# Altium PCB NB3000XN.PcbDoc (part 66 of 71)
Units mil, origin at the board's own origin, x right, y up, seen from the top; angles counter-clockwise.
Board outline 9527.56 x 6929.77 mil, 6 copper layers (Top Layer, GND+SHIELD, MidLayer1, MidLayer2, P2 - 3V3+5V0, Bottom Layer), stack 62.375 mil thick; 832 components, 1027 nets, 4655 pads, 4981 vias.
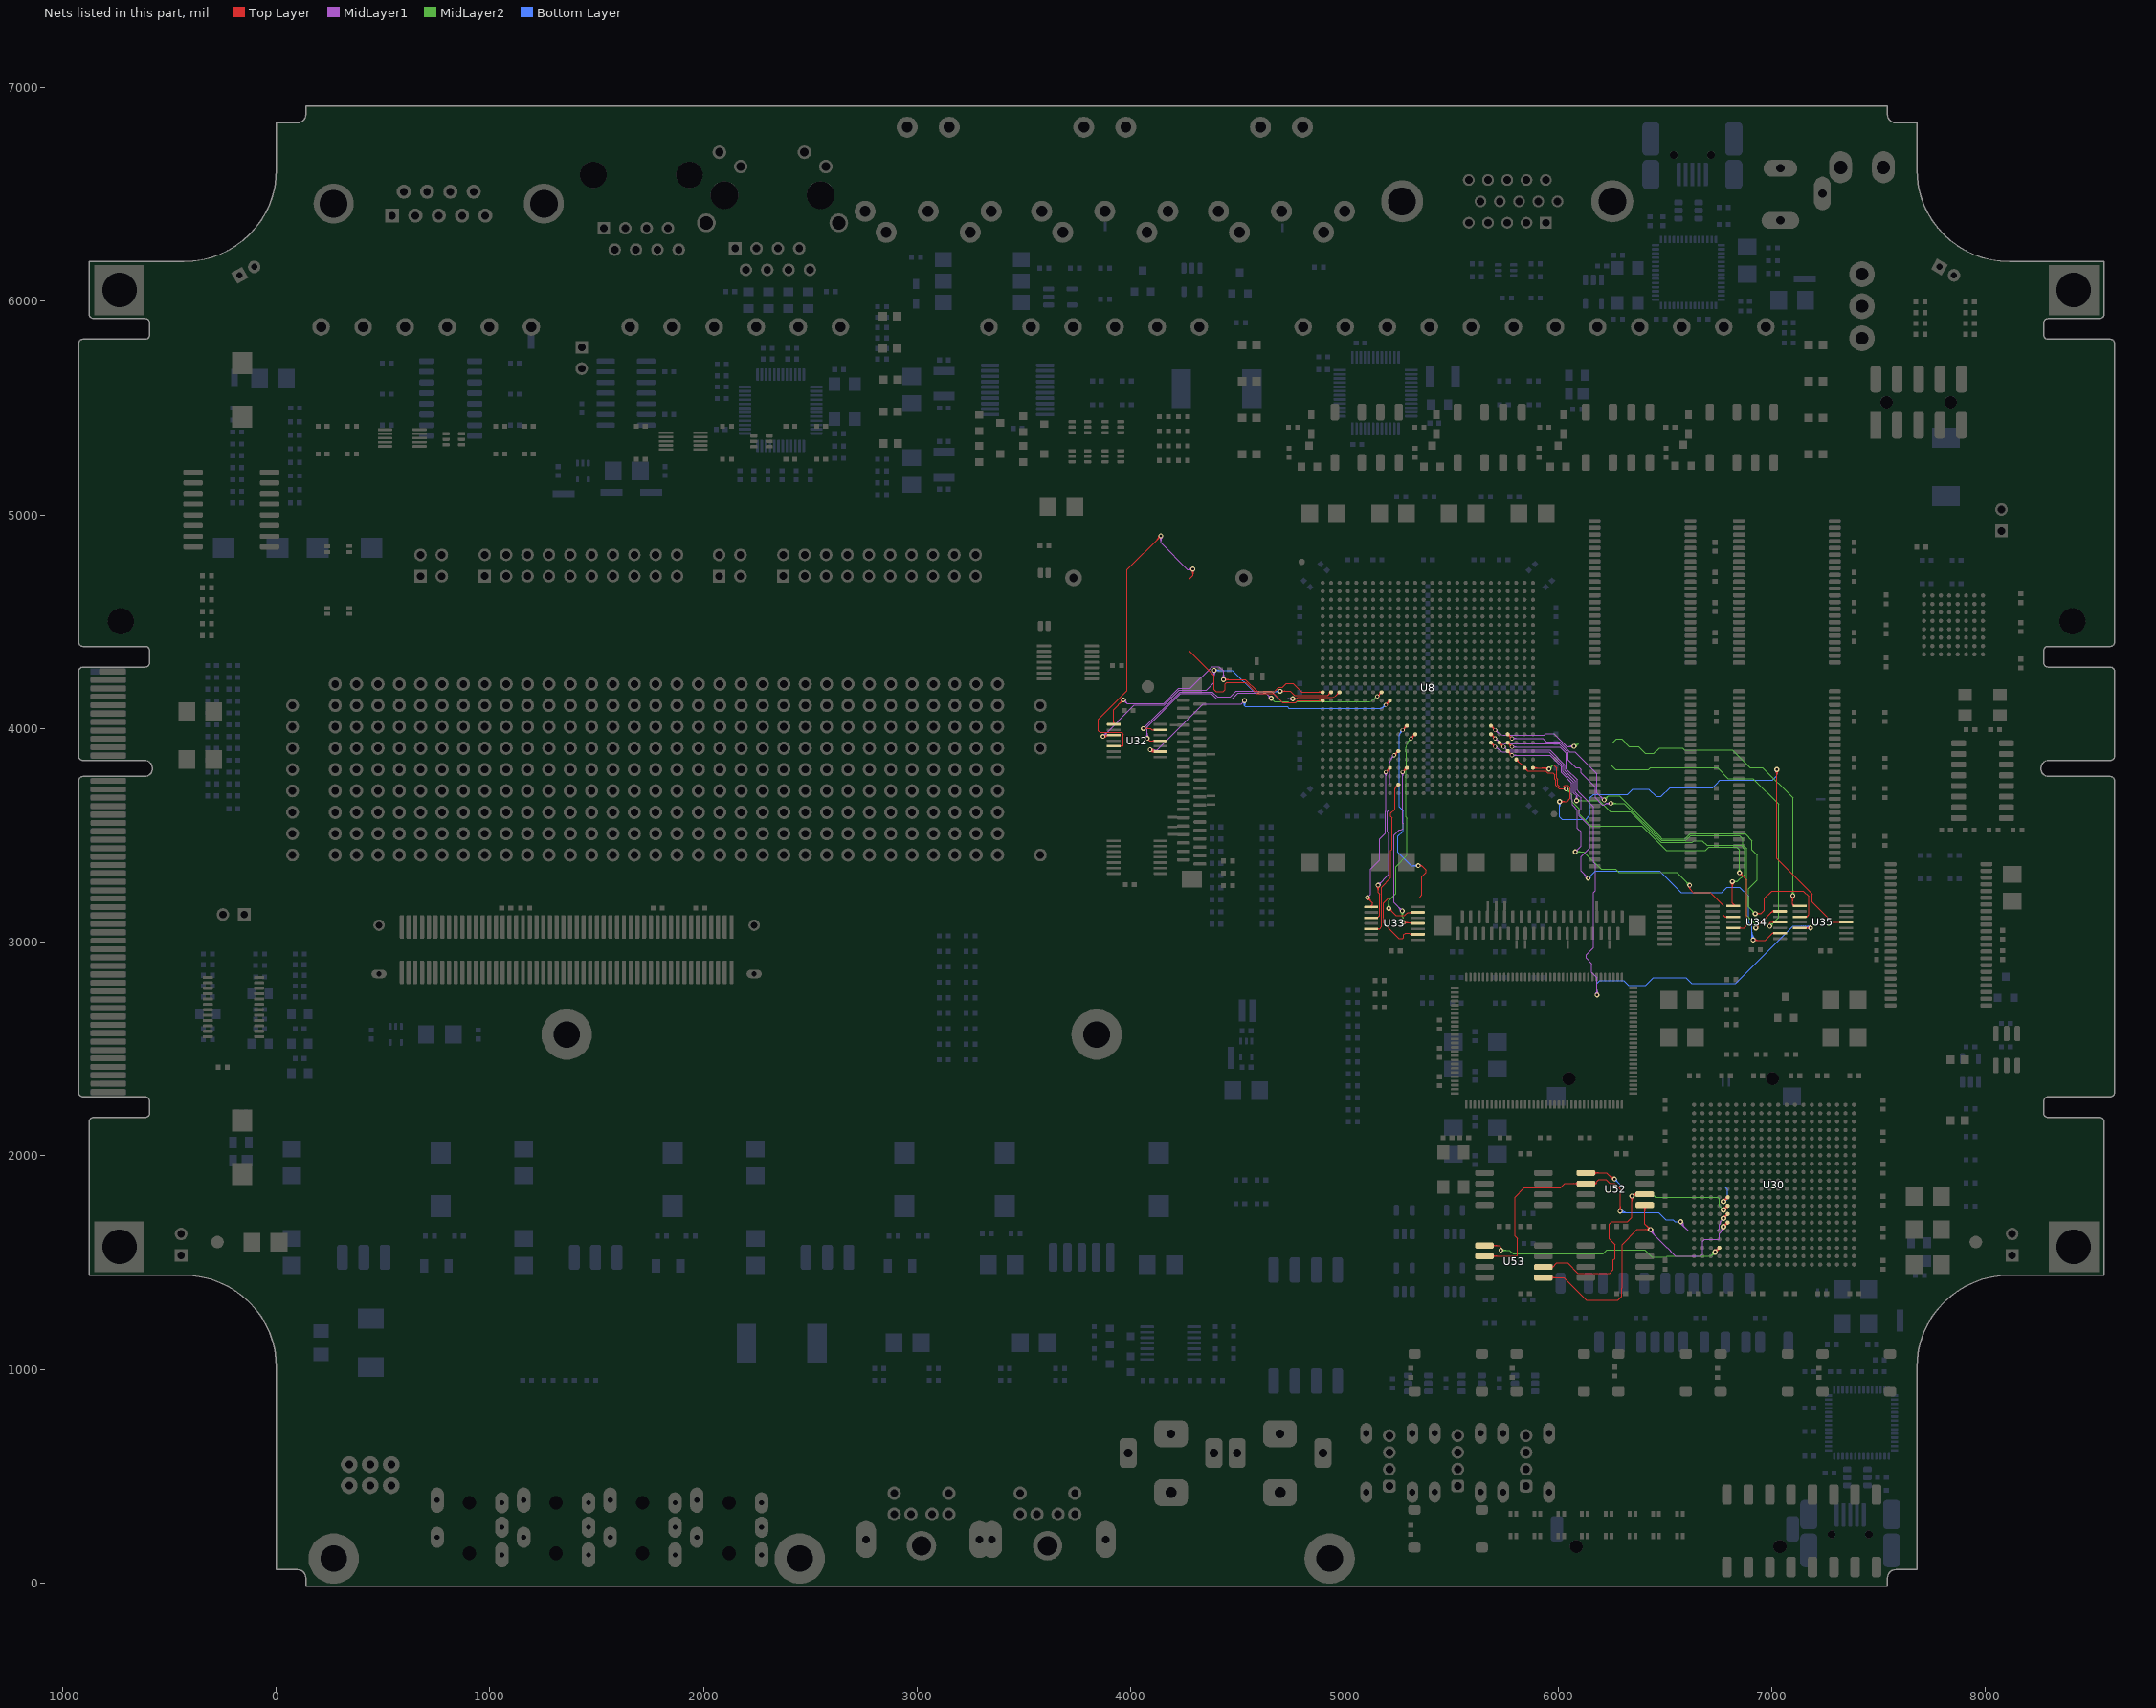
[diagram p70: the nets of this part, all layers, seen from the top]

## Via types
v1: diameter 23, hole 11.81, Top Layer to Bottom Layer, 3672 vias
v2: diameter 26, hole 11.81, Top Layer to Bottom Layer, 461 vias
v3: diameter 19, hole 11.81, Top Layer to Bottom Layer, tented both sides, 396 vias
v4: diameter 23.62, hole 11.81, Top Layer to Bottom Layer, 288 vias
v5: diameter 20, hole 11.81, Top Layer to Bottom Layer, 91 vias
v6: diameter 23, hole 11.81, Top Layer to Bottom Layer, tented both sides, 50 vias
v7: diameter 31, hole 11.81, Top Layer to Bottom Layer, 15 vias
v8: diameter 27.56, hole 11.81, Top Layer to Bottom Layer, tented both sides, 4 vias
v9: diameter 29, hole 11.81, Top Layer to Bottom Layer, 3 vias
v10: diameter 21, hole 11.81, Top Layer to Bottom Layer, 1 vias

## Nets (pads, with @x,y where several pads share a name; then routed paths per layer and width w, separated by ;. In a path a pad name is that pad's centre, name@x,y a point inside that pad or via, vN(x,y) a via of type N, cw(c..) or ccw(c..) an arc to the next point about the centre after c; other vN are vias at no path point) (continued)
USER_FLASH.DIN: U30.T15 U52.5 U53.5 | length 1959.8
  Top Layer w4: U53.5@5930.59,1430 6026.9,1430 6131.86,1325.04 6280.52,1325.04 6297.19,1341.71 6297.19,1380 6300,1382.81 6300,1585 6370.04,1655.04 v1(6431.86,1655.04) 6405.59,1681.31 U52.5@6405.59,1770 ; U53.5@5965.62,1424.5 cw(c5978.9,1411.22) 5978.9,1430 cw(c5978.9,1448.78) U53.5@5965.62,1435.5 ; U53.5@5968.45,1421.67 cw(c5988.56,1401.56) 5988.56,1430 cw(c5988.56,1458.44) U53.5@5968.45,1438.33 ; U52.5@6397.26,1761.67 cw(c6377.15,1741.56) 6405.59,1741.56 cw(c6434.03,1741.56) U52.5@6413.92,1761.67 ; U52.5@6400.09,1764.5 cw(c6386.81,1751.22) 6405.59,1751.22 cw(c6424.37,1751.22) U52.5@6411.09,1764.5 ; v1@6422.36,1655.04 ccw(c6399.42,1655.04) 6415.64,1671.26 ccw(c6431.86,1687.48) v1@6431.86,1664.54 ; v1@6425.14,1648.32 ccw(c6408.92,1632.11) 6408.92,1655.04 ccw(c6408.92,1677.98) v1@6425.14,1661.76 ; v1@6426.36,1655.04 ccw(c6413.08,1655.04) 6422.47,1664.43 ccw(c6431.86,1673.82) v1@6431.86,1660.54 ; v1@6427.97,1651.15 ccw(c6418.58,1641.76) 6418.58,1655.04 ccw(c6418.58,1668.32) v1@6427.97,1658.93
  Top Layer w8: v2(6773.78,1668.15) U30.T15@6793.46,1687.83 ; v2@6773.78,1677.15 ccw(c6773.78,1698.88) 6789.14,1683.51 ccw(c6804.51,1668.15) v2@6782.78,1668.15 ; U30.T15@6787.62,1687.83 cw(c6773.52,1687.83) 6783.49,1677.86 cw(c6793.46,1667.89) U30.T15@6793.46,1681.99
  MidLayer1 w4: v1(6431.86,1655.04) 6431.86,1646.71 6507.75,1570.81 6510.69,1570.81 6525.81,1555.69 6525.81,1552.75 6548.19,1530.37 6665.19,1530.37 6675.19,1540.37 6675.19,1600.04 6684.19,1609.04 6751.86,1609.04 6754.52,1611.71 6754.52,1636.71 6773.52,1655.71 v2@6773.52,1666.45 ; v1@6433.36,1655.04 ccw(c6457.1,1655.04) 6440.31,1638.25 ; v1@6437.36,1655.04 ccw(c6470.75,1655.04) 6447.14,1631.43 ; v1@6441.36,1655.04 ccw(c6484.41,1655.04) 6453.97,1624.6 ; 6760.62,1642.8 ccw(c6748.1,1655.32) v2@6763.94,1663.23 ; 6764.54,1646.73 ccw(c6753.33,1657.94) v2@6767.52,1665.02 ; 6768.47,1650.65 ccw(c6758.57,1660.55) v2@6771.1,1666.81 ; 6772.4,1654.58 ccw(c6763.81,1663.17) v2@6774.67,1668.6
USER_FLASH.DOUT: U30.T14 U52.2 U53.2 | length 2145.6
  Top Layer w4: U53.2@5655,1530 5805,1530 5810,1535 5810,1613.56 5798.52,1625.04 5798.52,1806.71 5841.86,1850.04 6011.23,1850.04 6031.19,1870 6177.97,1870 ; U53.2@5690.03,1524.5 cw(c5703.31,1511.22) 5703.31,1530 cw(c5703.31,1548.78) U53.2@5690.03,1535.5 ; U53.2@5692.86,1521.67 cw(c5712.97,1501.56) 5712.97,1530 cw(c5712.97,1558.44) U53.2@5692.86,1538.33 ; U52.2@6092.14,1861.67 ccw(c6072.03,1841.56) 6072.03,1870 ccw(c6072.03,1898.44) U52.2@6092.14,1878.33 ; U52.2@6094.97,1864.5 ccw(c6081.69,1851.22) 6081.69,1870 ccw(c6081.69,1888.78) U52.2@6094.97,1875.5 ; U52.2@6170.21,1865.05 cw(c6177.97,1861.45) 6177.97,1870 ; U52.2@6170.21,1874.95 ccw(c6177.97,1878.55) 6177.97,1870 ; v1@6283.47,1747.43 ccw(c6267.26,1763.64) 6290.19,1763.64 ccw(c6313.13,1763.64) v1@6296.91,1747.43 ; v1@6286.3,1744.6 ccw(c6276.91,1753.99) 6290.19,1753.99 ccw(c6303.47,1753.99) v1@6294.08,1744.6 ; v1(6290.19,1740.71) 6290.19,1845.04 6265.19,1870.04 6241.19,1870.04 6223.35,1887.88 6189.97,1887.88 6179.64,1877.55 6179.64,1871.67 6177.97,1870
  Top Layer w8: v2(6773.78,1707.52) U30.T14@6793.46,1727.2 ; v2@6773.78,1716.52 ccw(c6773.78,1738.25) 6789.14,1722.88 ccw(c6804.51,1707.52) v2@6782.78,1707.52 ; U30.T14@6787.62,1727.2 cw(c6773.52,1727.2) 6783.49,1717.23 cw(c6793.46,1707.26) U30.T14@6793.46,1721.36
  MidLayer1 w4: v1(6573.52,1691.71) 6573.52,1683.37 6608.52,1648.37 6744.19,1648.37 6754.19,1658.37 6754.19,1678.15 6758.64,1682.6 6758.64,1692.37 v2(6773.78,1707.52) ; v1@6575.02,1691.71 ccw(c6598.76,1691.71) 6581.98,1674.92 ; v1@6579.02,1691.71 ccw(c6612.42,1691.71) 6588.81,1668.09 ; v1@6583.02,1691.71 ccw(c6626.08,1691.71) 6595.63,1661.26
  Bottom Layer w4: v1@6288.42,1738.94 ccw(c6301.86,1752.38) 6301.86,1733.37 ; v1(6290.19,1740.71) 6297.52,1733.37 6469.86,1733.37 6503.19,1700.04 6537.98,1700.04 6546.31,1691.71 v1(6573.52,1691.71) ; v1@6291.25,1741.77 ccw(c6311.51,1762.03) 6311.51,1733.37 ; v1@6294.08,1744.6 ccw(c6321.17,1771.69) 6321.17,1733.37 ; v1@6296.91,1747.43 ccw(c6330.83,1781.35) 6330.83,1733.37
USER_FLASH.FLASH1_CS_N: U30.U18 U53.1 | length 1417.5
  Top Layer w4: U53.1@5655,1580 5725,1580 5731.86,1573.14 v1(5731.86,1558.37) ; U53.1@5690.03,1574.5 cw(c5703.31,1561.22) 5703.31,1580 cw(c5703.31,1598.78) U53.1@5690.03,1585.5 ; U53.1@5692.86,1571.67 cw(c5712.97,1551.56) 5712.97,1580 cw(c5712.97,1608.44) U53.1@5692.86,1588.33
  Top Layer w8: v2(6734.41,1550.04) U30.U18@6754.09,1569.72 ; v2@6734.41,1559.04 ccw(c6734.41,1580.77) 6749.77,1565.4 ccw(c6765.14,1550.04) v2@6743.41,1550.04 ; U30.U18@6748.25,1569.72 cw(c6734.15,1569.72) 6744.12,1559.75 cw(c6754.09,1549.78) U30.U18@6754.09,1563.88
  MidLayer2 w4: v1(5731.86,1558.37) 5771.67,1558.37 5788.67,1541.37 6210.88,1541.37 6228.54,1559.04 6406.19,1559.04 6434.52,1530.71 6438.04,1527.19 6507.38,1527.19 6510.9,1530.71 6715.08,1530.71 v2(6734.41,1550.04) ; v1@5735.75,1554.49 cw(c5745.14,1545.1) 5745.14,1558.37 cw(c5745.14,1571.65) v1@5735.75,1562.26 ; v1@5738.57,1551.66 cw(c5754.79,1535.44) 5754.79,1558.37 cw(c5754.79,1581.31) v1@5738.57,1565.09 ; v2@6723.41,1550.04 cw(c6696.85,1550.04) 6715.63,1531.26 cw(c6734.41,1512.49) v2@6734.41,1539.04 ; v2@6727.41,1550.04 cw(c6710.51,1550.04) 6722.46,1538.09 cw(c6734.41,1526.14) v2@6734.41,1543.04
USER_FLASH.FLASH2_CS_N: U30.T12 U52.1 | length 1120.8
  Top Layer w4: U52.1@6130,1920 6226.9,1920 6255.19,1891.71 v1(6263.52,1891.71) ; U52.1@6165.03,1914.5 cw(c6178.31,1901.22) 6178.31,1920 cw(c6178.31,1938.78) U52.1@6165.03,1925.5 ; U52.1@6167.86,1911.67 cw(c6187.97,1891.56) 6187.97,1920 cw(c6187.97,1948.44) U52.1@6167.86,1928.33 ; 6233.08,1913.82 ccw(c6263.53,1944.26) v1@6263.52,1901.21 ; 6239.91,1906.99 ccw(c6263.52,1930.61) v1@6263.52,1897.21 ; 6246.74,1900.16 ccw(c6263.52,1916.95) v1@6263.52,1893.21
  Top Layer w8: v2(6773.78,1786.26) U30.T12@6793.46,1805.94 ; v2@6773.78,1795.26 ccw(c6773.78,1816.99) 6789.14,1801.62 ccw(c6804.51,1786.26) v2@6782.78,1786.26 ; U30.T12@6787.62,1805.94 cw(c6773.52,1805.94) 6783.49,1795.97 cw(c6793.46,1786) U30.T12@6793.46,1800.1
  Bottom Layer w4: v1@6263.52,1882.21 cw(c6263.52,1859.27) 6279.74,1875.49 cw(c6295.96,1891.71) v1@6273.02,1891.71 ; v1@6263.52,1886.21 cw(c6263.52,1872.93) 6272.91,1882.32 cw(c6282.3,1891.71) v1@6269.02,1891.71 ; v1(6263.52,1891.71) 6299.86,1855.37 6779.19,1855.37 6792.86,1841.71 6792.86,1805.34 v2(6773.78,1786.26) ; v2@6773.78,1793.26 ccw(c6773.78,1810.16) 6785.73,1798.21 ccw(c6797.68,1786.26) v2@6780.78,1786.26 ; v2@6773.78,1797.26 ccw(c6773.78,1823.82) 6792.56,1805.04 ccw(c6811.33,1786.26) v2@6784.78,1786.26
USER_FLASH.SCLK: U30.T13 U52.6 U53.6 | length 1722.7
  Top Layer w4: U53.6@5930.59,1480 5975.9,1480 ; U53.6@5971.41,1476.65 cw(c5975.9,1475.32) 5975.9,1480 ; U53.6@5971.41,1483.35 ccw(c5975.9,1484.68) 5975.9,1480 ; v1@6338.14,1805.32 cw(c6321.92,1789.11) 6344.86,1789.11 cw(c6367.79,1789.11) 6351.57,1805.32 cw(c6387.01,1769.89) U52.6@6387.01,1820 ; v1@6340.97,1808.15 cw(c6331.58,1798.76) 6344.86,1798.76 cw(c6358.14,1798.76) 6348.75,1808.15 cw(c6377.35,1779.55) U52.6@6377.35,1820 ; v1@6343.09,1813.81 cw(c6358.04,1798.86) 6358.04,1820 ; v1@6345.92,1810.98 cw(c6367.69,1789.2) U52.6@6367.69,1820 ; U52.6@6366.56,1813.03 ccw(c6352.82,1802.95) v1@6352.82,1820 ; U52.6@6366.56,1826.97 cw(c6352.82,1837.05) v1@6352.82,1820 ; U52.6@6369.79,1815.4 ccw(c6360.71,1808.74) 6360.71,1820 ccw(c6360.71,1831.26) U52.6@6369.79,1824.6 ; U52.6@6405.59,1820 v1@6352.82,1820 ; 5975.9,1480 5994.27,1498.37 6043.86,1498.37 6092.19,1450.04 6241.52,1450.04 6258.48,1467 6258.48,1511.96 6266.52,1520 6266.52,1585.04 6240.19,1611.37 6240.19,1681.37 6250.52,1691.71 6323.52,1691.71 6344.86,1713.04 v1(6344.86,1812.04) v1@6352.82,1820
  Top Layer w8: v2(6773.78,1746.89) U30.T13@6793.46,1766.57 ; v2@6773.78,1755.89 ccw(c6773.78,1777.62) 6789.14,1762.25 ccw(c6804.51,1746.89) v2@6782.78,1746.89 ; U30.T13@6787.62,1766.57 cw(c6773.52,1766.57) 6783.49,1756.6 cw(c6793.46,1746.63) U30.T13@6793.46,1760.73
  MidLayer2 w4: v1(6344.86,1812.04) 6449,1812.04 6455,1806.04 6748.52,1806.04 6754.52,1800.04 6754.52,1766.37 6773.78,1747.12 v2(6773.78,1746.89) ; v1@6348.75,1808.15 cw(c6358.14,1798.76) 6358.14,1812.04 cw(c6358.14,1825.32) v1@6348.75,1815.93 ; v1@6351.57,1805.32 cw(c6367.79,1789.11) 6367.79,1812.04 cw(c6367.79,1834.98) v1@6351.57,1818.76
USER_LEDS.LED0.BLUE: U8.P2 U32.3 | length 1840.9
  Top Layer w4: v1(3869.52,3963.37) 3874.97,3968.82 U32.3@3920,3968.82 ; v1@3870.58,3962.31 cw(c3886.29,3946.61) 3886.29,3968.82 ; v1@3873.41,3959.49 cw(c3895.95,3936.95) U32.3@3895.95,3968.82 ; v1@3876.24,3956.66 cw(c3905.6,3927.29) U32.3@3905.6,3968.82 ; U32.3@3890.69,3965.99 ccw(c3883.86,3959.16) 3883.86,3968.82 ccw(c3883.86,3978.48) U32.3@3890.69,3971.65 ; v1(4698.52,4175.04) 4730,4175.04 4736,4175.04 4745.79,4175.04 4754.79,4166.04 4766.33,4154.5 4854.95,4154.5 4855.26,4154.81 4860,4154.81 4870,4154.81 4917.53,4154.81 ccw(c4917.53,4164.96) 4924.71,4157.78 ; v1@4702.41,4171.15 cw(c4711.8,4161.76) 4711.8,4175.04 cw(c4711.8,4188.32) v1@4702.41,4178.93 ; v1@4705.24,4168.32 cw(c4721.46,4152.11) 4721.46,4175.04 cw(c4721.46,4197.98) v1@4705.24,4181.76 ; U8.P2@4929.9,4170.31 cw(c4912.17,4170.31) 4924.71,4157.78 ; U8.P2@4937.24,4162.97 ccw(c4937.24,4145.25) 4924.71,4157.78
  MidLayer1 w4: v1(3869.52,3963.37) 4015.86,4109.71 ; v1@3869.52,3968.87 ccw(c3869.52,3982.15) 3878.91,3972.76 ccw(c3888.3,3963.37) v1@3875.02,3963.37 ; v1@3869.52,3972.87 ccw(c3869.52,3995.81) 3885.74,3979.59 ccw(c3901.96,3963.37) v1@3879.02,3963.37 ; 4136.17,4109.71 4015.86,4109.71 ; v1@4383.47,4265.99 cw(c4367.26,4249.77) 4390.19,4249.77 cw(c4413.13,4249.77) v1@4396.91,4265.99 ; v1@4386.3,4268.82 cw(c4376.91,4259.43) 4390.19,4259.43 cw(c4403.47,4259.43) v1@4394.08,4268.82 ; v1(4390.19,4272.71) 4390.19,4215.19 4355,4180 4227.17,4180 4156.88,4109.71 4015.86,4109.71
  Bottom Layer w4: v1(4390.19,4272.71) 4475.86,4272.71 4576.06,4172.5 4695.98,4172.5 v1(4698.52,4175.04) ; v1@4394.08,4268.82 cw(c4403.47,4259.43) 4403.47,4272.71 cw(c4403.47,4285.99) v1@4394.08,4276.6 ; v1@4396.91,4265.99 cw(c4413.13,4249.77) 4413.13,4272.71 cw(c4413.13,4295.64) v1@4396.91,4279.43 ; 4669.46,4172.5 ccw(c4669.46,4204.11) v1@4691.81,4181.76 ; 4679.11,4172.5 ccw(c4679.11,4194.45) v1@4694.64,4178.93 ; 4681.72,4172.5 cw(c4681.72,4158.24) v1@4691.81,4168.32
USER_LEDS.LED0.GREEN: U8.R1 U32.5 | length 2987.1
  Top Layer w4: U32.5@3920,3917.64 3962.64,3917.64 3965.19,3920.19 3965.19,3973.71 3956.86,3982.04 3856.86,3982.04 3848.52,3990.37 3848.52,4043.71 3981.86,4177.04 3981.86,4743.71 v1(4140.19,4902.04) ; U32.5@3949.31,3914.81 cw(c3956.14,3907.98) 3956.14,3917.64 cw(c3956.14,3927.3) U32.5@3949.31,3920.47 ; v1@4130.69,4902.04 cw(c4107.76,4902.04) 4123.97,4885.82 cw(c4140.19,4869.61) v1@4140.19,4892.54 ; v1@4134.69,4902.04 cw(c4121.41,4902.04) 4130.8,4892.65 cw(c4140.19,4883.26) v1@4140.19,4896.54 ; v1@4283.47,4739.99 cw(c4267.26,4723.77) 4290.19,4723.77 cw(c4313.13,4723.77) v1@4296.91,4739.99 ; v1@4286.3,4742.82 cw(c4276.91,4733.43) 4290.19,4733.43 cw(c4303.47,4733.43) v1@4294.08,4742.82 ; v1(4290.19,4746.71) 4290.19,4716.71 4273.19,4699.71 4273.19,4363.71 4291.13,4345.77 4390.19,4246.71 4390.19,4182.37 4398.52,4174.04 4431.86,4174.04 4440.19,4182.37 4440.19,4208.37 4448.52,4216.71 4537.21,4216.71 4589.42,4164.5 4667.4,4164.5 4682.44,4149.46 4710.86,4121.04 4769.52,4121.04 4779.43,4130.94 4860,4130.94 4870,4130.94 U8.R1@4897.87,4130.94 ; U8.R1@4892.57,4125.64 ccw(c4879.77,4112.84) 4879.77,4130.94 ccw(c4879.77,4149.05) U8.R1@4892.57,4136.25 ; U8.R1@4892.68,4125.75 ccw(c4880.15,4113.22) 4880.15,4130.94 ccw(c4880.15,4148.67) U8.R1@4892.68,4136.14
  MidLayer1 w4: v1@4133.47,4895.32 cw(c4117.26,4879.11) 4140.19,4879.11 cw(c4163.13,4879.11) v1@4146.91,4895.32 ; v1@4136.3,4898.15 cw(c4126.91,4888.76) 4140.19,4888.76 cw(c4153.47,4888.76) v1@4144.08,4898.15 ; v1(4140.19,4902.04) 4140.19,4869.69 4264.88,4745 ; 4271.38,4745 cw(c4271.38,4727.9) v1@4283.47,4739.99 ; 4273.91,4745 ccw(c4273.91,4761.48) v1@4286.12,4750.4 ; v1@4283.16,4753.09 cw(c4264.88,4769.68) 4264.88,4745 ; v1@4290,4745 4264.88,4745
USER_LEDS.LED0.RED: U8.P1 U32.1 | length 1547.5
  Top Layer w4: U32.1@3917.17,4022.83 ccw(c3910.34,4029.66) 3920,4029.66 ccw(c3929.66,4029.66) U32.1@3922.83,4022.83 ; U32.1@3920,4020 3920,4089.18 v1(3965.19,4134.37) ; v1@3955.69,4134.37 cw(c3932.76,4134.37) 3948.97,4118.16 cw(c3965.19,4101.94) v1@3965.19,4124.87 ; v1@3959.69,4134.37 cw(c3946.41,4134.37) 3955.8,4124.99 cw(c3965.19,4115.6) v1@3965.19,4128.87 ; v1(4433.52,4229.37) 4535.86,4229.37 4590.19,4175.04 4592.73,4172.5 4670.98,4172.5 4683.33,4184.84 4691.19,4192.71 4710.84,4192.71 4728.84,4210.71 4758.29,4210.71 4798.69,4170.31 4807.92,4170.31 4855.26,4170.31 4860,4170.31 4870,4170.31 U8.P1@4897.87,4170.31 ; v1@4437.41,4225.49 cw(c4446.8,4216.1) 4446.8,4229.37 cw(c4446.8,4242.65) v1@4437.41,4233.26 ; v1@4440.24,4222.66 cw(c4456.46,4206.44) 4456.46,4229.37 cw(c4456.46,4252.31) v1@4440.24,4236.09 ; U8.P1@4892.57,4165.01 ccw(c4879.77,4152.21) 4879.77,4170.31 ccw(c4879.77,4188.42) U8.P1@4892.57,4175.62 ; U8.P1@4892.68,4165.12 ccw(c4880.15,4152.59) 4880.15,4170.31 ccw(c4880.15,4188.04) U8.P1@4892.68,4175.51
  MidLayer1 w4: v1@3965.19,4124.87 cw(c3965.19,4101.94) 3981.41,4118.16 cw(c3997.63,4134.37) v1@3974.69,4134.37 ; v1@3965.19,4128.87 cw(c3965.19,4115.6) 3974.58,4124.99 cw(c3983.97,4134.37) v1@3970.69,4134.37 ; v1(3965.19,4134.37) 3981.86,4117.71 4153.56,4117.71 4223.86,4188 4278,4188 4380.21,4290.21 4412.05,4290.21 4433.52,4268.74 v1(4433.52,4229.37) ; v1@4426.81,4236.09 ccw(c4410.59,4252.31) 4433.52,4252.31 ccw(c4456.46,4252.31) v1@4440.24,4236.09 ; v1@4429.64,4233.26 ccw(c4420.25,4242.65) 4433.52,4242.65 ccw(c4446.8,4242.65) v1@4437.41,4233.26
USER_LEDS.LED1.BLUE: U8.P8 U32.11 | length 1593.3
  Top Layer w4: v1(4076.86,3954.37) 4088,3943.23 U32.11@4138.5,3943.23 ; U32.11@4109.2,3940.4 ccw(c4102.37,3933.57) 4102.37,3943.23 ccw(c4102.37,3952.89) U32.11@4109.2,3946.06 ; v3(5153.78,4150.63) U8.P8@5173.46,4170.31 ; U8.P8@5165.96,4170.31 cw(c5147.86,4170.31) 5160.66,4157.51 cw(c5173.46,4144.71) U8.P8@5173.46,4162.81 ; U8.P8@5166.12,4170.31 cw(c5148.4,4170.31) 5160.93,4157.78 cw(c5173.46,4145.25) U8.P8@5173.46,4162.97 ; 5166.58,4163.43 cw(c5153.78,4176.24) 5153.78,4158.13 ccw(c5153.78,4176.24) 5166.58,4163.43 ; 5166.58,4163.43 ccw(c5179.39,4150.63) 5161.28,4150.63 cw(c5179.39,4150.63) 5166.58,4163.43
  MidLayer1 w4: v1@4070.14,3961.09 ccw(c4053.92,3977.31) 4076.86,3977.31 ccw(c4099.79,3977.31) v1@4083.57,3961.09 ; v1@4072.97,3958.26 ccw(c4063.58,3967.65) 4076.86,3967.65 ccw(c4090.14,3967.65) v1@4080.75,3958.26 ; v1(4076.86,3954.37) 4076.86,4007.06 4233.8,4164 4376.23,4164 4400.52,4139.71 4474.19,4139.71 4501.19,4166.71 4597.23,4166.71 4599.44,4164.5 4620.56,4164.5 4622.77,4166.71 4631.86,4166.71 v1(4656.86,4141.71) ; v1@4647.36,4141.71 ccw(c4624.42,4141.71) 4640.64,4157.93 ccw(c4656.86,4174.14) v1@4656.86,4151.21 ; v1@4651.36,4141.71 ccw(c4638.08,4141.71) 4647.47,4151.1 ccw(c4656.86,4160.49) v1@4656.86,4147.21
  MidLayer2 w4: v1(4656.86,4141.71) 4671.8,4126.77 4735.52,4126.77 4741.52,4120.77 4771.52,4120.77 4777.52,4126.77 4855.26,4126.77 4860,4126.77 4870,4126.77 4997.36,4126.77 5016.78,4126.77 5090.9,4126.77 5110.4,4126.77 ccw(c5110.4,4168.5) 5139.91,4138.99 ; v3@5146.31,4151.28 cw(c5128.27,4152.86) 5139.91,4138.99 ; v3@5153.13,4143.16 ccw(c5151.55,4125.12) 5139.91,4138.99
USER_LEDS.LED1.GREEN: U8.P3 U32.13 | length 1313.1
  Top Layer w4: v1(4058.52,4000.04) 4092.89,4000.04 4098.52,3994.41 U32.13@4138.5,3994.41 ; v1@4062.41,3996.15 cw(c4071.8,3986.76) 4071.8,4000.04 cw(c4071.8,4013.32) v1@4062.41,4003.93 ; v1@4065.24,3993.32 cw(c4081.46,3977.11) 4081.46,4000.04 cw(c4081.46,4022.98) v1@4065.24,4006.76 ; U32.13@4109.2,3991.58 ccw(c4102.37,3984.75) 4102.37,3994.41 ccw(c4102.37,4004.07) U32.13@4109.2,3997.24 ; v1(4757.52,4139.37) 4773.52,4139.37 ; v1@4765.87,4134.83 cw(c4773.52,4130.65) 4773.52,4139.37 ; v1@4765.87,4143.92 ccw(c4773.52,4148.1) 4773.52,4139.37 ; U8.P3@4969.27,4170.31 cw(c4951.55,4170.31) 4964.08,4157.78 ; U8.P3@4976.61,4162.97 ccw(c4976.61,4145.25) 4964.08,4157.78 ; 4773.52,4139.37 4780.6,4146.45 4855.26,4146.45 4860,4146.45 4870,4146.45 4936.73,4146.45 ccw(c4936.73,4185.13) 4964.08,4157.78
  MidLayer1 w4: v1(4058.52,4000.04) 4230.48,4172 4381.23,4172 ; v1@4750.81,4132.66 ccw(c4734.59,4116.44) 4734.59,4139.37 ccw(c4734.59,4162.31) v1@4750.81,4146.09 ; v1@4753.64,4135.49 ccw(c4744.25,4126.1) 4744.25,4139.37 ccw(c4744.25,4152.65) v1@4753.64,4143.26 ; v1(4757.52,4139.37) 4692.86,4139.37 4657.19,4175.04 4619.79,4175.04 4617.25,4172.5 4602.75,4172.5 4600.21,4175.04 4493.19,4175.04 4465.86,4147.71 4405.52,4147.71 ; 4381.23,4172 4405.52,4147.71 ; 4381.23,4172 4405.52,4147.71
USER_LEDS.LED1.RED: U8.R9 U32.9 | length 1687.8
  Top Layer w4: v1@4088.42,3899.27 ccw(c4105.87,3916.72) 4105.87,3892.05 ; v1(4090.19,3901.04) 4090.19,3900.04 4098.18,3892.05 U32.9@4138.5,3892.05 ; v1@4091.25,3902.1 ccw(c4115.52,3926.37) U32.9@4115.52,3892.05 ; v1@4094.08,3904.93 ccw(c4125.18,3936.03) U32.9@4125.18,3892.05 ; v1@4096.91,3907.76 ccw(c4134.84,3945.69) U32.9@4134.84,3892.05 ; U32.9@4109.2,3889.22 ccw(c4102.37,3882.39) 4102.37,3892.05 ccw(c4102.37,3901.71) U32.9@4109.2,3894.88 ; v3(5193.15,4111.26) U8.R9@5212.83,4130.94 ; U8.R9@5205.33,4130.94 cw(c5187.23,4130.94) 5200.03,4118.14 cw(c5212.83,4105.34) U8.R9@5212.83,4123.44 ; U8.R9@5205.49,4130.94 cw(c5187.77,4130.94) 5200.3,4118.41 cw(c5212.83,4105.88) U8.R9@5212.83,4123.6 ; 5205.95,4124.06 cw(c5193.15,4136.87) 5193.15,4118.76 ccw(c5193.15,4136.87) 5205.95,4124.06 ; 5205.95,4124.06 ccw(c5218.76,4111.26) 5200.65,4111.26 cw(c5218.76,4111.26) 5205.95,4124.06
  MidLayer1 w4: v1(4090.19,3901.04) 4122.48,3901.04 4337.15,4115.71 4516.86,4115.71 v1(4531.86,4130.71) ; v1@4094.08,3897.15 cw(c4103.47,3887.76) 4103.47,3901.04 cw(c4103.47,3914.32) v1@4094.08,3904.93 ; v1@4096.91,3894.32 cw(c4113.13,3878.11) 4113.13,3901.04 cw(c4113.13,3923.98) v1@4096.91,3907.76
  Bottom Layer w4: v1@4525.14,4123.99 cw(c4508.92,4107.77) 4531.86,4107.77 cw(c4554.79,4107.77) v1@4538.57,4123.99 ; v1@4527.97,4126.82 cw(c4518.58,4117.43) 4531.86,4117.43 cw(c4545.14,4117.43) v1@4535.75,4126.82 ; v1(4531.86,4130.71) 4531.86,4107.37 4535.32,4103.92 4731.99,4103.92 4740.15,4095.75 4855.26,4095.75 4860,4095.75 4870,4095.75 5076.1,4095.75 5169.64,4095.75 ccw(c5169.64,4109.8) 5179.57,4099.87 ; v3@5185.68,4111.91 cw(c5167.64,4113.49) 5179.28,4099.62 cw(c5190.92,4085.75) v3@5192.5,4103.79
USER_LEDS.LED2.BLUE: U8.AA10 U33.3 | length 1124
  Top Layer w4: U33.3@5125,3113.82 5153.82,3113.82 5165.19,3125.19 5165.19,3225 5156.86,3233.33 v1(5156.86,3266.71) ; v1@5150.14,3259.99 cw(c5133.92,3243.77) 5156.86,3243.77 cw(c5179.79,3243.77) v1@5163.57,3259.99 ; U33.3@5151.48,3117.82 ccw(c5151.48,3133.12) 5162.3,3122.3 ; v1@5152.97,3262.82 cw(c5143.58,3253.43) 5156.86,3253.43 cw(c5170.14,3253.43) v1@5160.75,3262.82 ; v3(5232.52,3875.04) U8.AA10@5252.2,3894.72 ; U8.AA10@5244.7,3894.72 cw(c5226.6,3894.72) 5239.4,3881.92 cw(c5252.2,3869.12) U8.AA10@5252.2,3887.22 ; U8.AA10@5244.86,3894.72 cw(c5227.14,3894.72) 5239.67,3882.19 cw(c5252.2,3869.66) U8.AA10@5252.2,3887.38 ; 5245.32,3887.84 ccw(c5258.13,3875.04) 5240.02,3875.04 cw(c5258.13,3875.04) 5245.32,3887.84 ; 5245.32,3887.84 cw(c5232.52,3900.65) 5232.52,3882.54 ccw(c5232.52,3900.65) 5245.32,3887.84
  MidLayer1 w4: v1(5156.86,3266.71) 5207.86,3317.71 5207.86,3510.73 5200.86,3517.73 5200.86,3611.63 5208.66,3619.43 5208.66,3660 5208.66,3670 5208.66,3718.62 5208.66,3738.04 5208.66,3812.16 ; v1@5156.86,3272.21 ccw(c5156.86,3285.49) 5166.25,3276.1 ccw(c5175.64,3266.71) v1@5162.36,3266.71 ; v1@5156.86,3276.21 ccw(c5156.86,3299.14) 5173.07,3282.93 ccw(c5189.29,3266.71) v1@5166.36,3266.71 ; 5208.66,3798.23 5208.66,3812.16 ; v3@5225.05,3874.39 cw(c5207.01,3872.81) 5220.88,3861.17 ; v3@5233.17,3867.57 ccw(c5234.75,3849.53) 5220.88,3861.17 ; 5208.66,3812.16 5208.66,3831.66 cw(c5250.39,3831.66) 5220.88,3861.17
USER_LEDS.LED2.GREEN: U8.AE10 U33.5 | length 814.7
  Top Layer w4: U33.5@5125,3062.64 5163.52,3062.64 5173.52,3072.64 5173.52,3258.37 5216.19,3301.04 5216.19,3428.82 5222.02,3434.65 5222.02,3495.87 5222.02,3511 5222.02,3583.79 5217.02,3588.79 5217.02,3603.29 5236.7,3622.96 5236.7,3660 5236.7,3670 5236.7,3717.53 ; U33.5@5154.31,3059.81 cw(c5161.14,3052.98) 5161.14,3062.64 cw(c5161.14,3072.3) U33.5@5154.31,3065.47 ; 5236.7,3717.53 cw(c5246.85,3717.53) 5239.67,3724.71 ; 5236.7,3717.53 cw(c5246.85,3717.53) 5239.67,3724.71 ; 5239.67,3724.71 ccw(c5227.14,3737.24) 5244.86,3737.24 cw(c5227.14,3737.24) 5239.67,3724.71 ; 5239.67,3724.71 cw(c5252.2,3712.17) 5252.2,3729.9 ccw(c5252.2,3712.17) 5239.67,3724.71
USER_LEDS.LED2.RED: U8.AC9 U33.1 | length 980.9
  Top Layer w4: v1@5106.86,3198.87 cw(c5106.86,3175.94) 5123.07,3192.16 cw(c5139.29,3208.37) v1@5116.36,3208.37 ; v1@5106.86,3202.87 cw(c5106.86,3189.6) 5116.25,3198.99 cw(c5125.64,3208.37) v1@5112.36,3208.37 ; v1(5106.86,3208.37) 5131.86,3183.37 ; U33.1@5123.07,3168.5 ccw(c5114.88,3183.37) 5131.86,3183.37 ; U33.1@5126.93,3161.5 ccw(c5122.34,3169.84) U33.1@5131.86,3169.84 ; 5131.86,3176.6 cw(c5118.61,3176.6) U33.1@5125,3165 5131.86,3165 5131.86,3183.37 ; v3(5193.15,3796.3) U8.AC9@5212.83,3815.98 ; U8.AC9@5205.33,3815.98 cw(c5187.23,3815.98) 5200.03,3803.18 cw(c5212.83,3790.38) U8.AC9@5212.83,3808.48 ; U8.AC9@5205.49,3815.98 cw(c5187.77,3815.98) 5200.3,3803.45 cw(c5212.83,3790.92) U8.AC9@5212.83,3808.64 ; 5205.95,3809.1 cw(c5193.15,3821.91) 5193.15,3803.8 ccw(c5193.15,3821.91) 5205.95,3809.1 ; 5205.95,3809.1 ccw(c5218.76,3796.3) 5200.65,3796.3 cw(c5218.76,3796.3) 5205.95,3809.1
  MidLayer1 w4: v1(5106.86,3208.37) 5122.5,3224.02 5122.5,3343.06 5165.19,3385.75 5165.19,3483.37 5192.52,3510.71 5192.52,3613.14 5193.15,3613.77 5193.15,3660 5193.15,3670 5193.15,3718.62 v3(5193.15,3796.3) ; v3@5187.85,3791 cw(c5175.04,3778.19) 5193.15,3778.19 cw(c5211.26,3778.19) v3@5198.45,3791 ; v3@5187.96,3791.11 cw(c5175.42,3778.57) 5193.15,3778.57 cw(c5210.88,3778.57) v3@5198.34,3791.11
USER_LEDS.LED3.BLUE: U8.AC11 U33.11 | length 1249.3
  Top Layer w4: v3(5271.89,3796.3) U8.AC11@5291.57,3815.98 ; v1(5273.52,3091.71) 5306.86,3091.71 5310.19,3088.37 5310.19,3088.23 ; v1@5277.41,3087.82 cw(c5286.8,3078.43) 5286.8,3091.71 cw(c5286.8,3104.99) v1@5277.41,3095.6 ; v1@5280.24,3084.99 cw(c5296.46,3068.77) 5296.46,3091.71 cw(c5296.46,3114.64) v1@5280.24,3098.43 ; U8.AC11@5284.07,3815.98 cw(c5265.97,3815.98) 5278.77,3803.18 cw(c5291.57,3790.38) U8.AC11@5291.57,3808.48 ; U8.AC11@5284.23,3815.98 cw(c5266.51,3815.98) 5279.04,3803.45 cw(c5291.57,3790.92) U8.AC11@5291.57,3808.64 ; U33.11@5313.54,3086.27 ccw(c5310.19,3084.39) 5310.19,3088.23 ; U33.11@5313.54,3090.19 cw(c5310.19,3092.06) 5310.19,3088.23 ; U33.11@5343.5,3088.23 5310.19,3088.23 ; 5284.69,3809.1 ccw(c5297.5,3796.3) 5279.39,3796.3 cw(c5297.5,3796.3) 5284.69,3809.1 ; 5284.69,3809.1 cw(c5271.89,3821.91) 5271.89,3803.8 ccw(c5271.89,3821.91) 5284.69,3809.1
  MidLayer1 w4: v1@5260.69,3146.37 ccw(c5237.76,3146.37) 5253.97,3162.59 ccw(c5270.19,3178.81) v1@5270.19,3155.87 ; v1@5264.69,3146.37 ccw(c5251.41,3146.37) 5260.8,3155.76 ccw(c5270.19,3165.15) v1@5270.19,3151.87 ; v3@5266.59,3791 cw(c5253.78,3778.19) 5271.89,3778.19 cw(c5290,3778.19) v3@5277.19,3791 ; v3@5266.7,3791.11 cw(c5254.16,3778.57) 5271.89,3778.57 cw(c5289.62,3778.57) v3@5277.08,3791.11 ; v1(5270.19,3146.37) 5231.86,3184.71 5231.86,3500.67 5256.23,3525.04 5264.86,3525.04 5273.52,3533.71 5273.52,3555 5271.89,3556.63 5271.89,3660 5271.89,3670 5271.89,3718.62 v3(5271.89,3796.3)
  MidLayer2 w4: v1@5263.47,3139.66 cw(c5247.26,3123.44) 5270.19,3123.44 cw(c5293.13,3123.44) v1@5276.91,3139.66 ; v1@5266.3,3142.49 cw(c5256.91,3133.1) 5270.19,3133.1 cw(c5283.47,3133.1) v1@5274.08,3142.49 ; v1@5266.81,3098.43 ccw(c5250.59,3114.64) 5273.52,3114.64 ccw(c5296.46,3114.64) v1@5280.24,3098.43 ; v1@5269.64,3095.6 ccw(c5260.25,3104.99) 5273.52,3104.99 ccw(c5286.8,3104.99) v1@5277.41,3095.6 ; v1(5270.19,3146.37) 5270.19,3119.81 5273.52,3116.48 v1(5273.52,3091.71)
USER_LEDS.LED3.GREEN: U8.W12 U33.13 | length 1288.6
  Top Layer w4: v1@5206.86,3148.87 cw(c5206.86,3125.94) 5223.07,3142.16 cw(c5239.29,3158.37) v1@5216.36,3158.37 ; v1@5206.86,3152.87 cw(c5206.86,3139.6) 5216.25,3148.99 cw(c5225.64,3158.37) v1@5212.36,3158.37 ; v1(5206.86,3158.37) 5240.19,3125.04 5281.86,3125.04 5287.81,3130.99 5296.23,3139.41 U33.13@5343.5,3139.41 ; v3(5311.26,3953.78) U8.W12@5330.94,3973.46 ; U33.13@5314.2,3136.58 ccw(c5307.37,3129.75) 5307.37,3139.41 ccw(c5307.37,3149.07) U33.13@5314.2,3142.24 ; U8.W12@5323.44,3973.46 cw(c5305.34,3973.46) 5318.14,3960.66 cw(c5330.94,3947.86) U8.W12@5330.94,3965.96 ; U8.W12@5323.6,3973.46 cw(c5305.88,3973.46) 5318.41,3960.93 cw(c5330.94,3948.4) U8.W12@5330.94,3966.12 ; 5324.06,3966.58 ccw(c5336.87,3953.78) 5318.76,3953.78 cw(c5336.87,3953.78) 5324.06,3966.58 ; 5324.06,3966.58 cw(c5311.26,3979.39) 5311.26,3961.28 ccw(c5311.26,3979.39) 5324.06,3966.58
  MidLayer1 w4: v1@5205.19,3158.37 v1(5206.86,3158.37)
  MidLayer2 w4: v1@5200.14,3165.09 ccw(c5183.92,3181.31) 5206.86,3181.31 ccw(c5229.79,3181.31) v1@5213.57,3165.09 ; v1@5202.97,3162.26 ccw(c5193.58,3171.65) 5206.86,3171.65 ccw(c5220.14,3171.65) v1@5210.75,3162.26 ; v1(5206.86,3158.37) 5206.86,3194.37 5239.86,3227.37 5239.86,3353.34 5293.19,3406.67 5293.19,3580.37 5287.4,3586.17 5287.4,3660 5287.4,3670 5287.4,3690 ; 5287.4,3680.84 5287.4,3690 ; v3@5303.79,3953.13 cw(c5285.75,3951.55) 5299.62,3939.91 ; v3@5311.91,3946.31 ccw(c5313.49,3928.27) 5299.62,3939.91 ; 5287.4,3690 5287.4,3797.36 5287.4,3816.78 5287.4,3890.9 5287.4,3910.4 cw(c5329.13,3910.4) 5299.62,3939.91
USER_LEDS.LED3.RED: U8.V11 U33.9 | length 1630.4
  Top Layer w4: v3(5271.89,3993.15) U8.V11@5291.57,4012.83 ; U8.V11@5284.07,4012.83 cw(c5265.97,4012.83) 5278.77,4000.03 cw(c5291.57,3987.23) U8.V11@5291.57,4005.33 ; U8.V11@5284.23,4012.83 cw(c5266.51,4012.83) 5279.04,4000.3 cw(c5291.57,3987.77) U8.V11@5291.57,4005.49 ; U33.9@5314.07,3034.35 ccw(c5307.95,3028.76) 5307.95,3037.05 ; U33.9@5314.07,3039.75 cw(c5307.95,3045.33) 5307.95,3037.05 ; U33.9@5343.5,3037.05 5307.95,3037.05 ; v1(5345.19,3358.37) 5361.21,3358.37 ; v1@5353.53,3353.82 cw(c5361.21,3349.62) 5361.21,3358.37 ; v1@5353.53,3362.93 ccw(c5361.21,3367.13) 5361.21,3358.37 ; 5284.69,4005.95 cw(c5271.89,4018.76) 5271.89,4000.65 ccw(c5271.89,4018.76) 5284.69,4005.95 ; 5284.69,4005.95 ccw(c5297.5,3993.15) 5279.39,3993.15 cw(c5297.5,3993.15) 5284.69,4005.95 ; 5307.95,3037.05 5301.95,3043.05 5285.2,3043.05 5277.5,3035.35 5277.5,3022.35 5271.86,3016.71 5253.54,3016.71 5181.86,3088.39 5181.86,3183.37 5206.86,3208.37 5349.52,3208.37 5362.5,3221.35 5362.5,3306.68 5364.19,3308.37 5381.86,3326.04 5381.86,3337.73 5361.21,3358.37
  Bottom Layer w4: 5260.5,3979.57 ccw(c5270.43,3969.64) 5256.38,3969.64 5256.38,3876.1 5256.38,3670 5256.38,3660 5256.38,3633.3 5273.52,3616.16 5273.52,3519.37 5250,3495.85 5250,3420 5311.63,3358.37 v1(5345.19,3358.37) ; v3@5264.42,3992.5 cw(c5246.38,3990.92) 5260.25,3979.28 cw(c5274.12,3967.64) v3@5272.54,3985.68 ; v1@5338.47,3351.66 ccw(c5322.26,3335.44) 5322.26,3358.37 ccw(c5322.26,3381.31) v1@5338.47,3365.09 ; v1@5341.3,3354.49 ccw(c5331.91,3345.1) 5331.91,3358.37 ccw(c5331.91,3371.65) v1@5341.3,3362.26
USER_LEDS.LED4.BLUE: U8.AA23 U34.3 | length 2036.1
  Top Layer w4: U8.AA23@5764.02,3887.22 cw(c5764.02,3869.12) 5776.82,3881.92 cw(c5789.62,3894.72) U8.AA23@5771.52,3894.72 ; U8.AA23@5764.02,3887.38 cw(c5764.02,3869.66) 5776.55,3882.19 cw(c5789.08,3894.72) U8.AA23@5771.36,3894.72 ; U8.AA23@5764.02,3894.72 v3(5783.7,3875.04) ; v1@6610.35,3258.53 cw(c6605.32,3250.04) 6615.19,3250.04 ; v1(6615.19,3266.71) 6615.19,3250.04 ; v1@6620.03,3258.53 ccw(c6625.06,3250.04) 6615.19,3250.04 ; U34.3@6790.69,3115.99 ccw(c6783.86,3109.16) 6783.86,3118.82 ccw(c6783.86,3128.48) U34.3@6790.69,3121.65 ; U34.3@6820,3118.82 6781.18,3118.82 6773.52,3126.48 6773.52,3171.71 6711.86,3233.37 6631.86,3233.37 6615.19,3250.04 ; 5770.9,3887.84 cw(c5758.09,3875.04) 5776.2,3875.04 ccw(c5758.09,3875.04) 5770.9,3887.84 ; 5770.9,3887.84 ccw(c5783.7,3900.65) 5783.7,3882.54 cw(c5783.7,3900.65) 5770.9,3887.84
  MidLayer1 w4: v3(5783.7,3875.04) 5861.38,3875.04 5910,3875.04 5920,3875.04 5923.52,3875.04 5962.33,3875.04 6015,3822.37 6015,3794.9 6063.52,3746.37 6063.52,3670.04 6067.19,3666.37 6067.19,3641.71 6090.19,3618.71 6090.19,3533.37 6106.86,3516.71 6106.86,3450.04 v1(6079.86,3423.04) ; v3@5788.89,3869.85 cw(c5801.43,3857.31) 5801.43,3875.04 cw(c5801.43,3892.77) v3@5788.89,3880.23 ; v1@6079.86,3428.54 ccw(c6079.86,3441.82) 6089.25,3432.43 ccw(c6098.64,3423.04) v1@6085.36,3423.04 ; v1@6079.86,3432.54 ccw(c6079.86,3455.48) 6096.07,3439.26 ccw(c6112.29,3423.04) v1@6089.36,3423.04 ; 5801.81,3875.04 cw(c5801.81,3893.15) 5789,3880.34 ccw(c5801.81,3893.15) 5801.81,3875.04 ; 5801.81,3875.04 ccw(c5801.81,3856.93) 5789,3869.74 cw(c5801.81,3856.93) 5801.81,3875.04
  MidLayer2 w4: v1(6079.86,3423.04) 6119.56,3423.04 6200.9,3341.71 6267.56,3341.71 6283.23,3326.04 6555.86,3326.04 v1(6615.19,3266.71) ; v1@6083.75,3419.15 cw(c6093.14,3409.76) 6093.14,3423.04 cw(c6093.14,3436.32) v1@6083.75,3426.93 ; v1@6086.57,3416.32 cw(c6102.79,3400.11) 6102.79,3423.04 cw(c6102.79,3445.98) v1@6086.57,3429.76 ; v1@6605.69,3266.71 ccw(c6582.76,3266.71) 6598.97,3282.93 ccw(c6615.19,3299.14) v1@6615.19,3276.21 ; v1@6609.69,3266.71 ccw(c6596.41,3266.71) 6605.8,3276.1 ccw(c6615.19,3285.49) v1@6615.19,3272.21
USER_LEDS.LED4.GREEN: U8.AC25 U34.5 | length 1924.8
  Top Layer w4: v1(6037.47,3717.53) 6035.81,3719.19 6004.31,3719.19 5989.19,3734.31 5989.19,3759.75 5984.5,3764.44 5984.5,3783.46 5974.75,3793.21 5949.61,3793.21 5942.34,3800.48 5920,3800.48 5910,3800.48 5862.47,3800.48 ; U34.5@6815.19,3067.64 U34.5@6820,3067.64 6871.47,3067.64 6881.86,3078.02 6881.86,3291.71 v1(6848.52,3325.04) ; v1@6848.52,3315.54 cw(c6848.52,3292.61) 6864.74,3308.82 cw(c6880.96,3325.04) v1@6858.02,3325.04 ; v1@6848.52,3319.54 cw(c6848.52,3306.26) 6857.91,3315.65 cw(c6867.3,3325.04) v1@6854.02,3325.04 ; U34.5@6849.31,3064.81 cw(c6856.14,3057.98) 6856.14,3067.64 cw(c6856.14,3077.29) U34.5@6849.31,3070.47 ; 5855.29,3803.45 ccw(c5862.47,3810.63) 5862.47,3800.48 ; 5855.29,3803.45 ccw(c5862.47,3810.63) 5862.47,3800.48 ; 5855.29,3803.45 cw(c5867.83,3815.98) 5850.1,3815.98 ccw(c5867.83,3815.98) 5855.29,3803.45 ; 5855.29,3803.45 ccw(c5842.76,3790.92) 5842.76,3808.64 cw(c5842.76,3790.92) 5855.29,3803.45
  MidLayer2 w4: v1@6037.47,3708.03 cw(c6037.47,3685.1) 6053.69,3701.31 cw(c6069.9,3717.53) v1@6046.97,3717.53 ; v1@6037.47,3712.03 cw(c6037.47,3698.75) 6046.86,3708.14 cw(c6056.25,3717.53) v1@6042.97,3717.53 ; v1@6841.81,3331.76 ccw(c6825.59,3347.98) 6848.52,3347.98 ccw(c6871.46,3347.98) v1@6855.24,3331.76 ; v1@6844.64,3328.93 ccw(c6835.25,3338.32) 6848.52,3338.32 ccw(c6861.8,3338.32) v1@6852.41,3328.93 ; v1@6848.52,3316.71 v1(6848.52,3325.04) 6848.52,3431.48 6834.12,3445.88 6705.88,3445.88 6690,3430 6506.64,3430 6391.64,3545 6153.56,3545 6098.52,3600.04 6098.52,3625.04 6065.19,3658.37 6065.19,3689.81 v1@6039.22,3715.78 ; v1@6039.22,3715.78 6038.95,3715.78 6035,3719.73 6035,3720 v1(6037.47,3717.53) v1@6039.22,3715.78
USER_LEDS.LED4.RED: U8.Y21 U34.1 | length 2151
  Top Layer w4: U8.Y21@5685.28,3926.59 cw(c5685.28,3908.49) 5698.08,3921.29 cw(c5710.88,3934.09) U8.Y21@5692.78,3934.09 ; U8.Y21@5685.28,3926.75 cw(c5685.28,3909.03) 5697.81,3921.56 cw(c5710.34,3934.09) U8.Y21@5692.62,3934.09 ; U8.Y21@5685.28,3934.09 v3(5704.96,3914.41) ; v1@6808.47,3276.66 cw(c6792.26,3260.44) 6815.19,3260.44 cw(c6838.13,3260.44) v1@6821.91,3276.66 ; v1@6811.3,3279.49 cw(c6801.91,3270.1) 6815.19,3270.1 cw(c6828.47,3270.1) v1@6819.08,3279.49 ; v1(6815.19,3283.37) 6815.19,3183.37 6823.52,3175.04 6823.52,3170 U34.1@6820,3170 ccw(c6806.51,3172.62) 6816.23,3182.34 ; 6821.55,3177.02 cw(c6815.42,3170.89) U34.1@6823.93,3169.24 ; 5692.16,3927.21 cw(c5679.35,3914.41) 5697.46,3914.41 ccw(c5679.35,3914.41) 5692.16,3927.21 ; 5692.16,3927.21 ccw(c5704.96,3940.02) 5704.96,3921.91 cw(c5704.96,3940.02) 5692.16,3927.21
  MidLayer1 w4: v3@5706.26,3907.02 cw(c5709.41,3889.19) 5719.79,3904.02 ; v3@5712.35,3915.71 ccw(c5730.18,3918.86) 5719.79,3904.02 ; 5781.77,3890.55 5767.84,3890.55 ; v1@6079.67,3669.29 ccw(c6065.42,3684.39) 6086.19,3684.39 ; v1@6082.42,3666.38 ccw(c6074.17,3675.12) 6086.19,3675.12 ccw(c6098.21,3675.12) v1@6089.96,3666.38 ; v1(6086.19,3662.37) 6086.19,3684.39 ; v1@6092.71,3669.29 cw(c6106.96,3684.39) 6086.19,3684.39 ; 5719.79,3904.02 5728.37,3896.94 ccw(c5744.59,3914.32) 5744.42,3890.55 ; 5744.42,3890.55 ccw(c5744.59,3914.32) 5744.59,3890.55 ; 5744.42,3890.55 5744.59,3890.55 ; 5744.59,3890.55 5767.84,3890.55 ; 5767.84,3890.55 5841.96,3890.55 5861.38,3890.55 5910,3890.55 5920,3890.55 5958.14,3890.55 6023,3825.69 6023,3798.23 6037.59,3783.65 6072.35,3748.88 6072.35,3698.23 6086.19,3684.39
  MidLayer2 w4: v1(6086.19,3662.37) 6192.63,3662.37 6245,3610 6337.96,3610 6480.25,3467.71 6627.71,3467.71 6635,3475 6675,3475 6696.12,3453.88 6855,3453.88 6873.86,3435.02 6873.86,3318.86 6838.37,3283.37 v1(6815.19,3283.37) ; v1@6090.08,3658.49 cw(c6099.47,3649.1) 6099.47,3662.37 cw(c6099.47,3675.65) v1@6090.08,3666.26 ; v1@6092.91,3655.66 cw(c6109.13,3639.44) 6109.13,3662.37 cw(c6109.13,3685.31) v1@6092.91,3669.09 ; v1@6819.08,3279.49 cw(c6828.47,3270.1) 6828.47,3283.37 cw(c6828.47,3296.65) v1@6819.08,3287.26 ; v1@6821.91,3276.66 cw(c6838.13,3260.44) 6838.13,3283.37 cw(c6838.13,3306.31) v1@6821.91,3290.09
USER_LEDS.LED5.BLUE: U8.AC26 U34.11 | length 2147
  Top Layer w4: U8.AC26@5882.13,3815.98 5910,3815.98 5920,3815.98 5924.74,3815.98 ; U8.AC26@5887.32,3810.79 cw(c5899.85,3798.26) 5899.85,3815.98 cw(c5899.85,3833.71) U8.AC26@5887.32,3821.18 ; U8.AC26@5887.43,3810.68 cw(c5900.23,3797.88) 5900.23,3815.98 cw(c5900.23,3834.09) U8.AC26@5887.43,3821.29 ; 5933.44,3815.98 cw(c5933.44,3790.64) v1@5952.68,3807.13 ; 5942.13,3815.98 cw(c5942.13,3798.09) v1@5955.72,3809.73 ; v1@5949.64,3804.53 ccw(c5924.74,3783.2) 5924.74,3815.98 ; v1(5956.86,3810.71) 5951.58,3815.98 5924.74,3815.98 ; v1(6990.19,3075.04) 6990.19,3090.19 6993.23,3093.23 U34.11@7038.5,3093.23 ; U34.11@7009.2,3090.4 ccw(c7002.37,3083.57) 7002.37,3093.23 ccw(c7002.37,3102.89) U34.11@7009.2,3096.06
  MidLayer2 w4: v1(5956.86,3810.71) 5975.7,3829.56 6246.36,3829.56 6267.54,3808.37 6423.52,3808.37 6431.86,3816.71 6745.54,3816.71 6795.54,3766.71 6901.52,3766.71 6912.21,3766.71 7031.86,3647.06 7031.86,3116.71 v1(6990.19,3075.04) ; v1@5956.86,3816.21 ccw(c5956.86,3829.49) 5966.25,3820.1 ccw(c5975.64,3810.71) v1@5962.36,3810.71 ; v1@5956.86,3820.21 ccw(c5956.86,3843.14) 5973.07,3826.93 ccw(c5989.29,3810.71) v1@5966.36,3810.71 ; v1@6990.19,3080.54 ccw(c6990.19,3093.82) 6999.58,3084.43 ccw(c7008.97,3075.04) v1@6995.69,3075.04 ; v1@6990.19,3084.54 ccw(c6990.19,3107.48) 7006.41,3091.26 ccw(c7022.63,3075.04) v1@6999.69,3075.04
USER_LEDS.LED5.GREEN: U8.W21 U34.13 | length 2421.8
  Top Layer w4: U8.W21@5685.28,3965.96 cw(c5685.28,3947.86) 5698.08,3960.66 cw(c5710.88,3973.46) U8.W21@5692.78,3973.46 ; U8.W21@5685.28,3966.12 cw(c5685.28,3948.4) 5697.81,3960.93 cw(c5710.34,3973.46) U8.W21@5692.62,3973.46 ; U8.W21@5685.28,3973.46 v3(5704.96,3953.78) ; v1(6924.52,3066.71) 7005.82,3148 7036.6,3148 7038.5,3146.1 U34.13@7038.5,3144.41 ; v1@6924.52,3072.21 ccw(c6924.52,3085.49) 6933.91,3076.1 ccw(c6943.3,3066.71) v1@6930.02,3066.71 ; v1@6924.52,3076.21 ccw(c6924.52,3099.14) 6940.74,3082.93 ccw(c6956.96,3066.71) v1@6934.02,3066.71 ; 6988.47,3130.65 cw(c7012.02,3107.1) U34.13@7012.02,3140.41 ; 6995.3,3137.48 cw(c7012.02,3120.76) U34.13@7012.02,3144.41 ; 7002.13,3144.31 cw(c7012.02,3134.41) U34.13@7012.02,3148.41 ; 5692.16,3966.58 cw(c5679.35,3953.78) 5697.46,3953.78 ccw(c5679.35,3953.78) 5692.16,3966.58 ; 5692.16,3966.58 ccw(c5704.96,3979.39) 5704.96,3961.28 cw(c5704.96,3979.39) 5692.16,3966.58
  MidLayer1 w4: v3@5705.61,3946.31 cw(c5707.19,3928.27) 5718.83,3942.14 ; v3@5712.43,3954.43 ccw(c5730.47,3956.01) 5718.83,3942.14 ; 5781.77,3929.92 5767.84,3929.92 ; v1@6240.14,3643.32 ccw(c6223.92,3627.11) 6223.92,3650.04 ccw(c6223.92,3672.98) v1@6240.14,3656.76 ; v1@6242.97,3646.15 ccw(c6233.58,3636.76) 6233.58,3650.04 ccw(c6233.58,3663.32) v1@6242.97,3653.93 ; v1(6246.86,3650.04) 6222.99,3650.04 6214.65,3641.71 6206.86,3641.71 6173.52,3675.04 6173.52,3725.37 6106.86,3792.04 6106.86,3808.37 6098.52,3816.71 6083.29,3816.71 6047,3853 6047,3887.12 6004.2,3929.92 5920,3929.92 5910,3929.92 5861.38,3929.92 5841.96,3929.92 5767.84,3929.92 ; 5718.83,3942.14 ccw(c5748.34,3971.65) 5748.34,3929.92 5767.84,3929.92
  MidLayer2 w4: v1(6246.86,3650.04) 6309.23,3650.04 6483.56,3475.71 6596.82,3475.71 6621.15,3500.04 6848.52,3500.04 6865.19,3483.37 6865.19,3455 6881.86,3438.33 6881.86,3125.04 6924.52,3082.37 v1(6924.52,3066.71) ; v1@6250.75,3646.15 cw(c6260.14,3636.76) 6260.14,3650.04 cw(c6260.14,3663.32) v1@6250.75,3653.93 ; v1@6253.57,3643.32 cw(c6269.79,3627.11) 6269.79,3650.04 cw(c6269.79,3672.98) v1@6253.57,3656.76
USER_LEDS.LED5.RED: U8.Y22 U34.9 | length 2534.1
  Top Layer w4: U8.Y22@5724.65,3926.59 cw(c5724.65,3908.49) 5737.45,3921.29 cw(c5750.25,3934.09) U8.Y22@5732.15,3934.09 ; U8.Y22@5724.65,3926.75 cw(c5724.65,3909.03) 5737.18,3921.56 cw(c5749.71,3934.09) U8.Y22@5731.99,3934.09 ; U8.Y22@5724.65,3934.09 v3(5744.33,3914.41) ; v1(6912.52,3011.04) 6915.19,3008.37 6970,3008.37 7003.67,3042.05 ; v1@6916.41,3014.93 ccw(c6932.24,3030.76) 6932.24,3008.37 ; v1@6919.24,3004.32 cw(c6929.02,2994.54) 6929.02,3008.37 ; v1@6919.24,3017.76 ccw(c6941.9,3040.41) 6941.9,3008.37 ; U34.9@7008.91,3039.54 ccw(c7003.67,3035.33) 7003.67,3042.05 ; U34.9@7008.91,3044.55 cw(c7003.67,3048.76) 7003.67,3042.05 ; U34.9@7038.5,3042.05 7003.67,3042.05 ; 5731.53,3927.21 cw(c5718.72,3914.41) 5736.83,3914.41 ccw(c5718.72,3914.41) 5731.53,3927.21 ; 5731.53,3927.21 ccw(c5744.33,3940.02) 5744.33,3921.91 cw(c5744.33,3940.02) 5731.53,3927.21
  MidLayer1 w4: v3@5744.98,3906.94 cw(c5746.56,3888.9) 5758.2,3902.77 cw(c5769.84,3916.64) v3@5751.8,3915.06 ; 5757.91,3903.02 ccw(c5767.84,3912.95) 5767.84,3898.9 5861.38,3898.9 5910,3898.9 5920,3898.9 5961.1,3898.9 6031,3829 6031,3803.56 6080.35,3754.21 6080.35,3701.55 6091.37,3690.53 6106.86,3675.04 6106.86,3623.37 6098.52,3615.04 6098.52,3591.71 6148.52,3541.71 6148.52,3441.71 6106.86,3400.04 6106.86,3332.37 v1(6140.19,3299.04) ; v1@6130.69,3299.04 ccw(c6107.76,3299.04) 6123.97,3315.26 ccw(c6140.19,3331.48) v1@6140.19,3308.54 ; v1@6134.69,3299.04 ccw(c6121.41,3299.04) 6130.8,3308.43 ccw(c6140.19,3317.82) v1@6140.19,3304.54
  Bottom Layer w4: v1(6140.19,3299.04) 6174.52,3333.37 6474.63,3333.37 6574.63,3233.37 6765.19,3233.37 6789.52,3257.71 6849.19,3257.71 6890.19,3216.71 6890.19,3091.71 6906.86,3075.04 6906.86,3016.71 v1(6912.52,3011.04) ; v1@6140.19,3304.54 ccw(c6140.19,3317.82) 6149.58,3308.43 ccw(c6158.97,3299.04) v1@6145.69,3299.04 ; v1@6140.19,3308.54 ccw(c6140.19,3331.48) 6156.41,3315.26 ccw(c6172.63,3299.04) v1@6149.69,3299.04 ; 6906.86,3028.34 ccw(c6929.83,3028.34) v1@6913.58,3012.1 ; 6906.86,3038 ccw(c6939.48,3038) v1@6916.41,3014.93 ; 6906.86,3047.66 ccw(c6949.14,3047.66) v1@6919.24,3017.76
USER_LEDS.LED6.BLUE: U8.W23 U35.3 | length 2729
  Top Layer w4: U8.W23@5764.02,3965.96 cw(c5764.02,3947.86) 5776.82,3960.66 cw(c5789.62,3973.46) U8.W23@5771.52,3973.46 ; U8.W23@5764.02,3966.12 cw(c5764.02,3948.4) 5776.55,3960.93 cw(c5789.08,3973.46) U8.W23@5771.36,3973.46 ; U8.W23@5764.02,3973.46 v3(5783.7,3953.78) ; v1(6922.52,3133.37) 6948.52,3133.37 6965.19,3150.04 6965.19,3205.39 6999.8,3240 7147.25,3240 7173.52,3213.73 7173.52,3128.52 ; v1@6926.41,3129.49 cw(c6935.8,3120.1) 6935.8,3133.37 cw(c6935.8,3146.65) v1@6926.41,3137.26 ; v1@6929.24,3126.66 cw(c6945.46,3110.44) 6945.46,3133.37 cw(c6945.46,3156.31) v1@6929.24,3140.09 ; U35.3@7130,3118.82 7163.82,3118.82 ; U35.3@7156.48,3118.82 ccw(c7158.1,3132.31) 7167.7,3122.7 ; U35.3@7156.96,3122.79 ccw(c7159.34,3142.71) 7173.52,3128.52 ; U35.3@7159.84,3116.65 cw(c7163.82,3114.09) 7163.82,3118.82 ; U35.3@7159.84,3120.99 ccw(c7163.82,3123.55) 7163.82,3118.82 ; 5770.9,3966.58 cw(c5758.09,3953.78) 5776.2,3953.78 ccw(c5758.09,3953.78) 5770.9,3966.58 ; 5770.9,3966.58 ccw(c5783.7,3979.39) 5783.7,3961.28 cw(c5783.7,3979.39) 5770.9,3966.58 ; 7163.82,3118.82 7173.52,3128.52
  MidLayer1 w4: v3(5783.7,3953.78) 5861.38,3953.78 5910,3953.78 5920,3953.78 5928.12,3953.78 5942.9,3939 6006.43,3939 6053.73,3891.71 6077.86,3891.71 6181.86,3787.71 6181.86,3699.04 v1(6215.19,3665.71) ; v3@5788.89,3948.59 cw(c5801.43,3936.05) 5801.43,3953.78 cw(c5801.43,3971.51) v3@5788.89,3958.97 ; v3@5789,3948.48 cw(c5801.81,3935.67) 5801.81,3953.78 cw(c5801.81,3971.89) v3@5789,3959.08 ; v1@6205.69,3665.71 ccw(c6182.76,3665.71) 6198.97,3681.93 ccw(c6215.19,3698.14) v1@6215.19,3675.21 ; v1@6209.69,3665.71 ccw(c6196.41,3665.71) 6205.8,3675.1 ccw(c6215.19,3684.49) v1@6215.19,3671.21
  MidLayer2 w4: v1(6215.19,3665.71) 6234.48,3685 6285.58,3685 6474.77,3495.81 6486.88,3483.71 6593.5,3483.71 6618.17,3508.37 6874.52,3508.37 6907.86,3475.04 6907.86,3432.37 6931.86,3408.37 6931.86,3291.71 6890.19,3250.04 6890.19,3165.71 v1(6922.52,3133.37) ; v1@6215.19,3671.21 ccw(c6215.19,3684.49) 6224.58,3675.1 ccw(c6233.97,3665.71) v1@6220.69,3665.71 ; v1@6215.19,3675.21 ccw(c6215.19,3698.14) 6231.41,3681.93 ccw(c6247.63,3665.71) v1@6224.69,3665.71 ; v1@6913.02,3133.37 ccw(c6890.09,3133.37) 6906.31,3149.59 ccw(c6922.52,3165.81) v1@6922.52,3142.87 ; v1@6917.02,3133.37 ccw(c6903.75,3133.37) 6913.13,3142.76 ccw(c6922.52,3152.15) v1@6922.52,3138.87
USER_LEDS.LED6.GREEN: U8.Y23 U35.5 | length 3272.9
  Top Layer w4: U8.Y23@5764.02,3926.59 cw(c5764.02,3908.49) 5776.82,3921.29 cw(c5789.62,3934.09) U8.Y23@5771.52,3934.09 ; U8.Y23@5764.02,3926.75 cw(c5764.02,3909.03) 5776.55,3921.56 cw(c5789.08,3934.09) U8.Y23@5771.36,3934.09 ; U8.Y23@5764.02,3934.09 v3(5783.7,3914.41) ; U35.5@7130,3067.64 7180.93,3067.64 v1(7181.86,3066.71) ; U35.5@7156.68,3067.64 cw(c7156.68,3041.53) v1@7175.14,3059.99 ; U35.5@7159.31,3064.81 cw(c7166.14,3057.98) 7166.14,3067.64 cw(c7166.14,3077.29) U35.5@7159.31,3070.47 ; U35.5@7161.17,3067.64 ccw(c7161.17,3087.4) v1@7175.14,3073.43 ; 7166.33,3067.64 cw(c7166.33,3051.18) v1@7177.97,3062.82 ; 5770.9,3927.21 cw(c5758.09,3914.41) 5776.2,3914.41 ccw(c5758.09,3914.41) 5770.9,3927.21 ; 5770.9,3927.21 ccw(c5783.7,3940.02) 5783.7,3921.91 cw(c5783.7,3940.02) 5770.9,3927.21
  MidLayer1 w4: v3(5783.7,3914.41) 5861.38,3914.41 5910,3914.41 5920,3914.41 5924.74,3914.41 ; v3@5788.89,3909.22 cw(c5801.43,3896.68) 5801.43,3914.41 cw(c5801.43,3932.14) v3@5788.89,3919.6 ; 5925.07,3914.41 6008.4,3914.41 6039,3883.81 6039,3809.56 6088.35,3760.21 6088.35,3711.21 6095.86,3703.7 6165.19,3634.37 6165.19,3374.43 6174.19,3365.43 6174.19,3241.71 6165.19,3232.71 6165.19,2975.04 6131.86,2941.71 6131.86,2925.04 6156.86,2900.04 6156.86,2858.37 6181.86,2833.37 v1(6181.86,2752.71) ; v1@6175.14,2759.43 ccw(c6158.92,2775.64) 6181.86,2775.64 ccw(c6204.79,2775.64) v1@6188.57,2759.43 ; v1@6177.97,2756.6 ccw(c6168.58,2765.99) 6181.86,2765.99 ccw(c6195.14,2765.99) v1@6185.75,2756.6 ; 5801.81,3914.41 cw(c5801.81,3932.52) 5789,3919.71 ccw(c5801.81,3932.52) 5801.81,3914.41 ; 5801.81,3914.41 ccw(c5801.81,3896.3) 5789,3909.11 cw(c5801.81,3896.3) 5801.81,3914.41
  Bottom Layer w4: v1@6175.14,2759.43 ccw(c6158.92,2775.64) 6181.86,2775.64 ccw(c6204.79,2775.64) v1@6188.57,2759.43 ; v1@6177.97,2756.6 ccw(c6168.58,2765.99) 6181.86,2765.99 ccw(c6195.14,2765.99) v1@6185.75,2756.6 ; v1(6181.86,2752.71) 6181.86,2806.37 6195.52,2820.04 6305.9,2820.04 6328.56,2797.37 6410.17,2797.37 6446.17,2833.37 6598.52,2833.37 6623.86,2808.04 6831.52,2808.04 6840.19,2816.71 7098.52,3075.04 7173.52,3075.04 v1(7181.86,3066.71) ; 7138.8,3075.04 cw(c7138.8,3023.66) v1@7175.14,3059.99 ; 7148.46,3075.04 cw(c7148.46,3033.31) v1@7177.97,3062.82 ; 7158.12,3075.04 cw(c7158.12,3042.97) v1@7180.8,3065.65 ; 7167.78,3075.04 cw(c7167.78,3052.63) v1@7183.62,3068.48
USER_LEDS.LED6.RED: U8.V21 U35.1 | length 2515.8
  Top Layer w4: U8.V21@5685.28,4005.33 cw(c5685.28,3987.23) 5698.08,4000.03 cw(c5710.88,4012.83) U8.V21@5692.78,4012.83 ; U8.V21@5685.28,4005.49 cw(c5685.28,3987.77) 5697.81,4000.3 cw(c5710.34,4012.83) U8.V21@5692.62,4012.83 ; U8.V21@5685.28,4012.83 v3(5704.96,3993.15) ; v1@7091.81,3211.66 cw(c7079.61,3199.46) 7096.86,3199.46 ; 7096.24,3178.51 cw(c7088.31,3170.57) U35.1@7099.52,3170.15 ; 7096.86,3191.42 cw(c7125.48,3191.42) v1@7105.24,3211.66 ; 7096.86,3201.07 cw(c7115.83,3201.07) v1@7102.41,3214.49 ; v1@7096.86,3216.71 7096.86,3177.89 7104.75,3170 U35.1@7130,3170 ; 7098.79,3175.96 ccw(c7103.52,3180.69) U35.1@7103.52,3174 ; 5692.16,4005.95 cw(c5679.35,3993.15) 5697.46,3993.15 ccw(c5679.35,3993.15) 5692.16,4005.95 ; 5692.16,4005.95 ccw(c5704.96,4018.76) 5704.96,4000.65 cw(c5704.96,4018.76) 5692.16,4005.95
  MidLayer1 w4: v3@5705.61,3985.68 cw(c5707.19,3967.64) 5718.83,3981.51 ; v3@5712.43,3993.8 ccw(c5730.47,3995.38) 5718.83,3981.51 ; 5781.77,3969.29 5767.84,3969.29 ; v1@6066.81,3909.99 ccw(c6050.59,3893.77) 6050.59,3916.71 ccw(c6050.59,3939.64) v1@6066.81,3923.43 ; v1@6069.64,3912.82 ccw(c6060.25,3903.43) 6060.25,3916.71 ccw(c6060.25,3929.99) v1@6069.64,3920.6 ; v1(6073.52,3916.71) 6040.04,3916.71 5979.6,3977.15 5942.3,3977.15 5934.79,3969.64 5934.64,3969.64 5934.29,3969.29 5920,3969.29 5910,3969.29 5861.38,3969.29 5841.96,3969.29 5767.84,3969.29 ; 5718.83,3981.51 ccw(c5748.34,4011.02) 5748.34,3969.29 5767.84,3969.29
  MidLayer2 w4: v1(6073.52,3916.71) 6081.86,3916.71 6098.52,3933.37 ; v1@6073.79,3918.18 ccw(c6076.57,3933.67) 6087.7,3922.55 ; v1@6074.5,3922.12 ccw(c6078.21,3942.85) 6093.11,3927.96 ; v1@6075.2,3926.06 ccw(c6079.86,3952.04) 6098.52,3933.37 ; v1@7091.81,3225.09 ccw(c7075.59,3241.31) 7098.52,3241.31 ccw(c7121.46,3241.31) v1@7105.24,3225.09 ; v1@7094.64,3222.26 ccw(c7085.25,3231.65) 7098.52,3231.65 ccw(c7111.8,3231.65) v1@7102.41,3222.26 ; v1(7098.52,3218.37) 7098.52,3675.04 6956.86,3816.71 6897.52,3816.71 6814.19,3900.04 6590.19,3900.04 6581.86,3908.37 6473.52,3908.37 6448.52,3883.37 6408.52,3883.37 6375.19,3916.71 6331.86,3916.71 6297.52,3951.04 6273.19,3951.04 6255.52,3933.37 6123.12,3933.37 6098.52,3933.37
USER_LEDS.LED7.BLUE: U8.AB24 U35.11 | length 3059.9
  Top Layer w4: 5924.74,3831.49 5920,3831.49 ; v1(6006.86,3658.37) 6042.52,3658.37 6056.86,3672.71 6056.86,3722.89 6044.72,3735.03 6030.22,3735.03 6022.38,3727.19 6007.62,3727.19 5997.19,3737.62 5997.19,3763.06 5992.5,3767.75 5992.5,3815.48 5976.48,3831.49 5920,3831.49 ; v1@6010.75,3654.49 cw(c6020.14,3645.1) 6020.14,3658.37 cw(c6020.14,3671.65) v1@6010.75,3662.26 ; v1@6013.57,3651.66 cw(c6029.79,3635.44) 6029.79,3658.37 cw(c6029.79,3681.31) v1@6013.57,3665.09 ; v1@7016.81,3801.66 cw(c7000.59,3785.44) 7023.52,3785.44 cw(c7046.46,3785.44) v1@7030.24,3801.66 ; v1@7019.64,3804.49 cw(c7010.25,3795.1) 7023.52,3795.1 cw(c7036.8,3795.1) v1@7027.41,3804.49 ; v1(7023.52,3808.37) 7023.52,3391.71 7139.99,3275.24 7140.19,3275.04 ; 7315.19,3093.23 7283.32,3093.23 7189.52,3187.02 7189.52,3225.71 ; 5815.92,3842.82 ccw(c5843.27,3870.17) 5843.27,3831.49 ; 5815.92,3842.82 ccw(c5843.27,3870.17) 5843.27,3831.49 ; 5815.92,3842.82 ccw(c5803.39,3830.29) 5803.39,3848.01 cw(c5803.39,3830.29) 5815.92,3842.82 ; 5815.92,3842.82 cw(c5828.45,3855.35) 5810.73,3855.35 ccw(c5828.45,3855.35) 5815.92,3842.82 ; 5843.27,3831.49 5885.56,3831.49 5910,3831.49 5920,3831.49 ; 7140.19,3275.04 7189.52,3225.71 ; 7140.19,3275.04 7189.52,3225.71
  Bottom Layer w4: v1@6000.14,3651.66 cw(c5983.92,3635.44) 6006.86,3635.44 cw(c6029.79,3635.44) v1@6013.57,3651.66 ; v1@6002.97,3654.49 cw(c5993.58,3645.1) 6006.86,3645.1 cw(c6020.14,3645.1) v1@6010.75,3654.49 ; v1(6006.86,3658.37) 6006.86,3585.35 6017.5,3574.71 6123.19,3574.71 ; 6040.19,3575.04 6123.52,3575.04 ; v1@7016.81,3801.66 cw(c7000.59,3785.44) 7023.52,3785.44 cw(c7046.46,3785.44) v1@7030.24,3801.66 ; v1@7019.64,3804.49 cw(c7010.25,3795.1) 7023.52,3795.1 cw(c7036.8,3795.1) v1@7027.41,3804.49 ; v1(7023.52,3808.37) 7023.52,3780 7002.23,3758.71 6757.19,3758.71 6740.19,3741.71 6722.52,3724.04 6524.19,3724.04 6481.86,3681.71 6458.52,3681.71 6423.52,3716.71 6348.52,3716.71 6323.52,3691.71 6165.19,3691.71 6148.52,3675.04 6148.52,3594.69 6128.88,3575.04 ; 6123.19,3574.71 6128.54,3574.71 6128.88,3575.04 ; 6123.19,3574.71 6123.52,3575.04 ; 6123.52,3575.04 6128.88,3575.04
